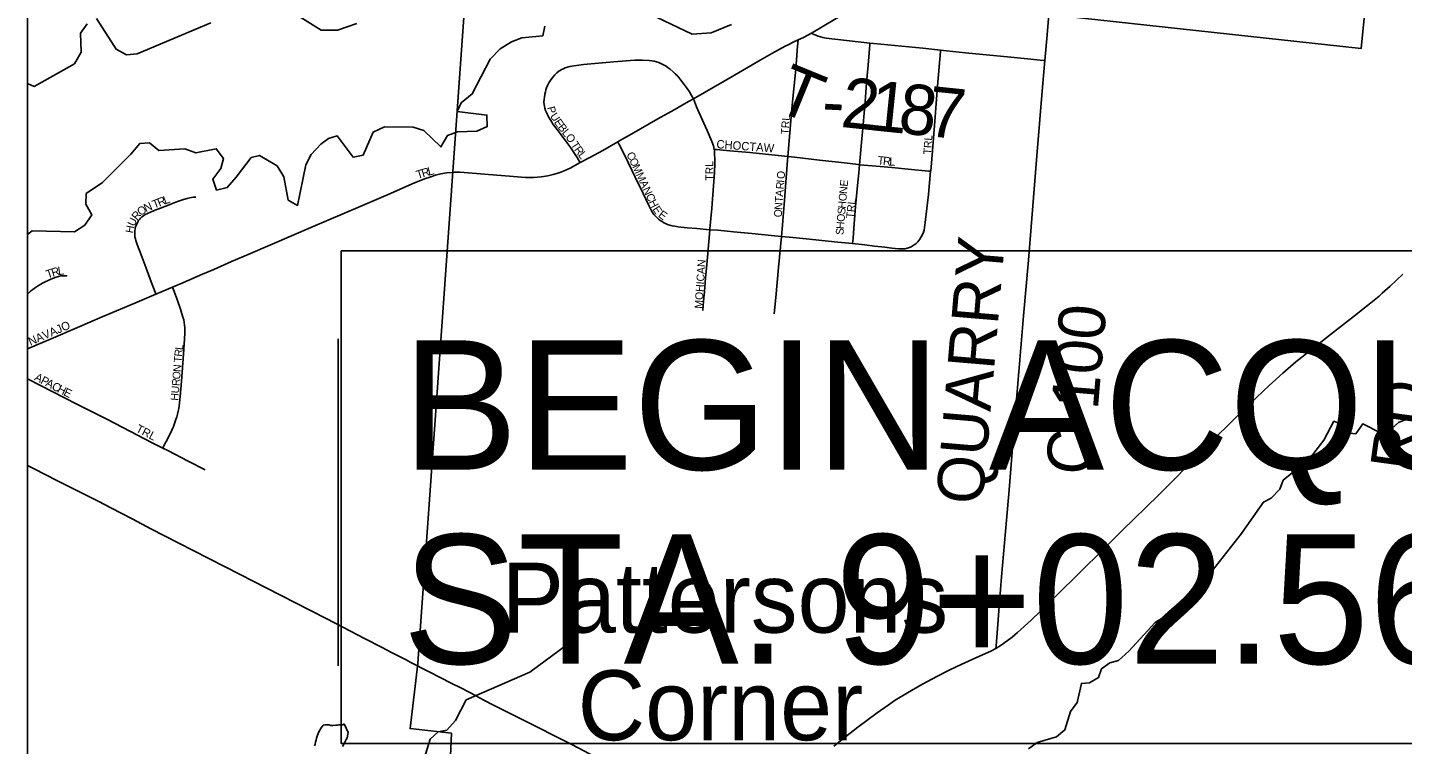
# Model space of a CAD drawing. Extents: x -13.9 to 69.1, y -25.2 to 26.1.
# Drawn here: x 1.757 to 3.245, y 16.445 to 17.221 of the extents above; entities that cross this region are included whole.
import ezdxf

# ---------------------------------------------------------------- set-up
doc = ezdxf.new("R2010")
doc.units = 0
for name, color, linetype in [('Default', 7, 'Continuous'), ('GM_X_Corporation', 7, 'Continuous'), ('GM_X_County_Road', 7, 'Continuous'), ('GM_X_County_Road_Text', 7, 'Continuous'), ('GM_X_Major_Lake', 7, 'Continuous'), ('GM_X_Minor_Lake', 7, 'Continuous'), ('GM_X_Minor_River', 7, 'Continuous'), ('GM_X_Township', 7, 'Continuous'), ('GM_X_Township_Road', 7, 'Continuous'), ('GM_X_Township_Road_Text', 7, 'Continuous'), ('GM_X_Township_Subdivision', 7, 'Continuous'), ('GM_X_Township_Subdivision_Text', 7, 'Continuous'), ('GM_X_Unincorporated_Text', 7, 'Continuous'), ('SH_Data', 7, 'Continuous'), ('SH_Text', 7, 'Continuous')]:
    doc.layers.add(name, color=color, linetype=linetype)

msp = doc.modelspace()

# ---------------------------------------------------------------- linework, layer by layer
at = {"layer": 'Default'}
msp.add_lwpolyline([(2.0933, 16.53), (2.0933, 16.8836)], dxfattribs=at)
at = {"layer": 'GM_X_Corporation'}
msp.add_lwpolyline([(3.2881, 17.4999), (3.2328, 17.5244), (3.2004, 17.1978), (2.8622, 17.2345), (2.8637, 17.2542), (2.8698, 17.3211), (2.9058, 17.3174), (2.9211, 17.4915), (2.9741, 17.4881), (2.979, 17.5484), (2.9644, 17.5499), (2.969, 17.6021), (3.0384, 17.5954), (3.0351, 17.5999), (2.9416, 17.7344), (3.085, 17.8742), (3.0797, 17.8807), (3.2331, 17.8445), (3.2716, 17.8354)], dxfattribs=at)
at = {"layer": 'GM_X_County_Road'}
for points in [[(2.8581, 17.1847), (2.8604, 17.2124), (2.8622, 17.2345)], [(2.8051, 16.5488), (2.8054, 16.5517), (2.8088, 16.5988), (2.8111, 16.626), (2.8164, 16.6876), (2.8193, 16.7202), (2.8223, 16.7569), (2.8267, 16.8097), (2.8299, 16.8481), (2.8351, 16.9085), (2.8402, 16.9689), (2.8494, 17.0815), (2.856, 17.1602), (2.8581, 17.1847)], [(2.8051, 16.5488), (2.8108, 16.5523), (2.8174, 16.5568), (2.8228, 16.561), (2.8284, 16.5658), (2.8431, 16.5794), (2.8633, 16.5988), (2.8768, 16.612), (2.8899, 16.6248), (2.9021, 16.6369), (2.9147, 16.6494), (2.9285, 16.6631), (2.9407, 16.6751), (2.9559, 16.6899), (2.9661, 16.7), (2.9828, 16.7164), (2.9959, 16.7292), (3.032, 16.766), (3.0442, 16.7782), (3.0567, 16.7907), (3.0694, 16.8031), (3.087, 16.8202), (3.1008, 16.8331), (3.1155, 16.8465), (3.1297, 16.8588), (3.1443, 16.8705), (3.1671, 16.8883), (3.1931, 16.9085), (3.2073, 16.9198), (3.2197, 16.93), (3.2231, 16.933), (3.2316, 16.9406), (3.2453, 16.9535)], [(1.7571, 16.7467), (1.7644, 16.7429), (1.7889, 16.7305), (1.8118, 16.7187), (1.8344, 16.7075), (1.8473, 16.7008), (1.8712, 16.6885), (1.8905, 16.6782), (1.9054, 16.6704), (1.9364, 16.6547), (1.9873, 16.6287), (2.0153, 16.6144), (2.0632, 16.5899), (2.0802, 16.5812), (2.0991, 16.5713), (2.1219, 16.5593), (2.1409, 16.5496), (2.1504, 16.5448), (2.1668, 16.5363), (2.1713, 16.5339)], [(2.6298, 16.4431), (2.6422, 16.4531), (2.6556, 16.4635), (2.6766, 16.4789), (2.6885, 16.4875), (2.6959, 16.4927), (2.7094, 16.5008), (2.725, 16.5097), (2.7418, 16.5188), (2.7537, 16.5249), (2.7628, 16.5293), (2.7801, 16.537), (2.794, 16.5431), (2.7996, 16.5458), (2.805, 16.5487), (2.8051, 16.5488)], [(2.1713, 16.5339), (2.1916, 16.5233), (2.2156, 16.5111), (2.2266, 16.5056), (2.2426, 16.4973), (2.2454, 16.4958)], [(2.2454, 16.4958), (2.2599, 16.4882), (2.2774, 16.4793), (2.291, 16.4726), (2.346, 16.4446), (2.3783, 16.4279), (2.4137, 16.4096), (2.4441, 16.3939), (2.471, 16.3799), (2.5073, 16.3611), (2.5227, 16.3528)]]:
    msp.add_lwpolyline(points, dxfattribs=at)
at = {"layer": 'GM_X_Major_Lake'}
for points in [[(2.1136, 17.2249), (2.0925, 17.2178), (2.0749, 17.2175), (2.0327, 17.2439)], [(2.4311, 17.2348), (2.4765, 17.2134), (2.4968, 17.2148), (2.5189, 17.2237)], [(1.8218, 17.2245), (1.8145, 17.2145), (1.8151, 17.1938), (1.8081, 17.1813), (1.7644, 17.1565), (1.7571, 17.1598)], [(1.7571, 16.9967), (1.7622, 17.0004), (1.808, 16.9993), (1.8193, 17.0067), (1.8266, 17.0178), (1.8201, 17.0295), (1.8207, 17.0408), (1.8382, 17.0527), (1.8691, 17.0836), (1.8785, 17.095), (1.889, 17.0958), (1.8992, 17.0876), (1.9273, 17.0891), (1.9393, 17.0848), (1.9613, 17.0894), (1.9692, 17.0787), (1.9663, 17.0678), (1.9576, 17.0564), (1.9618, 17.0447), (1.9733, 17.0473), (1.983, 17.0587), (1.9992, 17.0798), (2.0081, 17.0821), (2.0274, 17.0708), (2.0346, 17.059), (2.0391, 17.0338), (2.0494, 17.0281), (2.0584, 17.0718), (2.0641, 17.083), (2.0744, 17.0943), (2.083, 17.1003), (2.0921, 17.1034), (2.1095, 17.0804), (2.1204, 17.0824), (2.131, 17.1072), (2.1433, 17.1131), (2.1746, 17.1127), (2.186, 17.1091), (2.2045, 17.0913), (2.2115, 17.1035), (2.2224, 17.1076), (2.2433, 17.1085), (2.2546, 17.1133), (2.2542, 17.1257), (2.2219, 17.1297), (2.2264, 17.1391), (2.2384, 17.1486), (2.2578, 17.1863), (2.2685, 17.1973), (2.2808, 17.205), (2.292, 17.2094), (2.3146, 17.2114), (2.3169, 17.2219)], [(1.9554, 17.2254), (1.8758, 17.192), (1.8643, 17.1908), (1.8529, 17.1969), (1.8471, 17.2061), (1.8317, 17.2301)]]:
    msp.add_lwpolyline(points, dxfattribs=at)
at = {"layer": 'GM_X_Minor_Lake'}
for points in [[(2.0997, 16.4673), (2.0983, 16.4662), (2.0963, 16.4659), (2.0939, 16.4659), (2.0923, 16.4656), (2.0906, 16.4656), (2.0875, 16.4653), (2.0855, 16.4653), (2.0835, 16.4661), (2.0818, 16.4661), (2.0794, 16.4661), (2.0771, 16.4658), (2.075, 16.4629), (2.0719, 16.4578), (2.0705, 16.4538), (2.0698, 16.4517), (2.0695, 16.4498), (2.0688, 16.4473), (2.0684, 16.4451), (2.0677, 16.4433)], [(2.0981, 16.4426), (2.0995, 16.4452), (2.1005, 16.4473), (2.1019, 16.4502), (2.1029, 16.452), (2.1036, 16.456), (2.104, 16.4578), (2.0997, 16.4673)]]:
    msp.add_lwpolyline(points, dxfattribs=at)
at = {"layer": 'GM_X_Minor_River'}
for points in [[(3.2591, 16.8007), (3.2408, 16.7933), (3.2298, 16.7833), (3.2207, 16.7824), (3.2023, 16.7918), (3.1947, 16.781), (3.1849, 16.7819), (3.1797, 16.7911), (3.1709, 16.7945), (3.1599, 16.7739), (3.1444, 16.7538), (3.1161, 16.7307), (3.1122, 16.721), (3.103, 16.7113), (3.0945, 16.7071), (3.079, 16.6848), (3.071, 16.6729), (3.0312, 16.6224), (2.9953, 16.5881), (2.9776, 16.5767), (2.9488, 16.5456), (2.9379, 16.5356), (2.9284, 16.5332), (2.9192, 16.5268), (2.916, 16.5174), (2.9065, 16.5114), (2.8977, 16.5108), (2.893, 16.4902), (2.8858, 16.4805), (2.8798, 16.4606), (2.8706, 16.4532), (2.8499, 16.447), (2.8404, 16.4402)], [(2.1864, 16.4298), (2.1928, 16.4504), (2.2014, 16.4586), (2.2108, 16.4603), (2.2204, 16.4707), (2.2319, 16.493), (2.3008, 16.5231), (2.3407, 16.5526)]]:
    msp.add_lwpolyline(points, dxfattribs=at)
at = {"layer": 'GM_X_Township'}
for points in [[(2.2023, 16.145), (2.216, 16.457), (2.1711, 16.462), (2.1794, 16.5325), (2.2304, 17.2467), (2.5714, 18.9023), (2.5995, 20.0118)], [(1.7571, 19.5083), (1.7571, 15.7823)], [(7.8661, 18.459), (4.5288, 18.7816), (2.5714, 18.9023), (2.2304, 17.2467), (2.1794, 16.5325), (2.1711, 16.462), (2.216, 16.457), (2.2023, 16.145)]]:
    msp.add_lwpolyline(points, dxfattribs=at)
at = {"layer": 'GM_X_Township_Road'}
for points in [[(2.6054, 17.2143), (2.6066, 17.2138), (2.6102, 17.2121), (2.6127, 17.211), (2.6154, 17.2103), (2.6179, 17.2097), (2.6213, 17.2091), (2.6687, 17.2037)], [(2.6687, 17.2037), (2.673, 17.2032), (2.7259, 17.1981), (2.7453, 17.196)], [(2.7453, 17.196), (2.7516, 17.1953), (2.7722, 17.1931), (2.8212, 17.1884), (2.8394, 17.1865), (2.8565, 17.1849), (2.8581, 17.1847)]]:
    msp.add_lwpolyline(points, dxfattribs=at)
at = {"layer": 'GM_X_Township_Subdivision'}
for points in [[(2.6054, 17.2143), (2.6304, 17.2292), (2.645, 17.2377), (2.6592, 17.2457), (2.6909, 17.2638), (2.7061, 17.2723), (2.7429, 17.2928), (2.7459, 17.2943)], [(2.4777, 17.1434), (2.511, 17.1624), (2.5309, 17.1741), (2.5498, 17.1851), (2.5626, 17.1923), (2.5769, 17.2002), (2.5811, 17.2023), (2.5856, 17.2046), (2.591, 17.2071)], [(2.58, 17.0811), (2.5821, 17.1065), (2.5843, 17.1328), (2.5884, 17.1753), (2.5904, 17.2002), (2.591, 17.2071)], [(2.591, 17.2071), (2.5911, 17.2071), (2.5968, 17.2098), (2.601, 17.212), (2.6054, 17.2143)], [(2.6574, 17.0721), (2.6598, 17.096), (2.6615, 17.1155), (2.6636, 17.1401), (2.6652, 17.1607), (2.6671, 17.1841), (2.6686, 17.2022), (2.6687, 17.2037)], [(2.7344, 17.065), (2.7345, 17.0653), (2.7356, 17.0781), (2.7388, 17.1145), (2.7412, 17.1478), (2.7424, 17.1615), (2.7453, 17.1945), (2.7453, 17.196)], [(2.3552, 17.0744), (2.3546, 17.0755), (2.352, 17.0797), (2.3491, 17.0843), (2.3451, 17.0903), (2.3419, 17.0948), (2.3391, 17.0985), (2.3366, 17.1019), (2.3334, 17.1059), (2.3313, 17.1086), (2.3261, 17.1155), (2.3233, 17.1198), (2.321, 17.1237), (2.3198, 17.126), (2.3186, 17.1286), (2.3178, 17.1308), (2.3171, 17.1333), (2.3166, 17.1353), (2.3163, 17.1372), (2.316, 17.1398), (2.3162, 17.143), (2.3165, 17.1452), (2.317, 17.1483), (2.3176, 17.151), (2.3181, 17.1532), (2.3189, 17.1553), (2.3199, 17.1578), (2.3213, 17.1607), (2.3228, 17.1629), (2.3244, 17.1654), (2.3258, 17.1673), (2.3276, 17.1693), (2.33, 17.1716), (2.332, 17.1732), (2.3336, 17.1741), (2.3351, 17.175), (2.337, 17.1759), (2.3389, 17.1768), (2.3416, 17.1777), (2.344, 17.1783), (2.3463, 17.1788), (2.3589, 17.1805), (2.3914, 17.1832), (2.4145, 17.185), (2.4227, 17.1852), (2.4298, 17.1848), (2.4327, 17.1845), (2.4354, 17.184), (2.4377, 17.1835), (2.4394, 17.1829), (2.4417, 17.1821), (2.444, 17.181), (2.4461, 17.1799), (2.4483, 17.1786), (2.4505, 17.177), (2.4527, 17.1753), (2.4557, 17.1725), (2.4581, 17.1703), (2.4607, 17.1677), (2.4631, 17.1649), (2.4679, 17.1588), (2.4711, 17.1545), (2.4734, 17.1508), (2.4757, 17.1469), (2.4777, 17.1434)], [(2.396, 17.0969), (2.3987, 17.0985), (2.4085, 17.1041), (2.4417, 17.123), (2.4542, 17.1301), (2.4725, 17.1404), (2.4777, 17.1434)], [(2.5002, 17.0886), (2.4994, 17.0924), (2.4977, 17.0973), (2.4926, 17.1091), (2.4839, 17.1281), (2.4812, 17.1346), (2.4777, 17.1434)], [(2.3552, 17.0744), (2.3657, 17.08), (2.3797, 17.0876), (2.396, 17.0969)], [(2.396, 17.0969), (2.3975, 17.094), (2.4034, 17.0819), (2.4147, 17.0587), (2.4234, 17.0408), (2.429, 17.0285), (2.432, 17.0229), (2.4335, 17.0204), (2.435, 17.0183), (2.4366, 17.0164), (2.4383, 17.0149), (2.44, 17.0131), (2.4419, 17.0117), (2.4438, 17.0105), (2.4457, 17.0093), (2.4477, 17.0084), (2.4498, 17.0075), (2.4521, 17.0067), (2.4546, 17.0061), (2.4577, 17.0054), (2.4611, 17.0049), (2.471, 17.0039), (2.4814, 17.0029), (2.4954, 17.0017)], [(2.4954, 17.0017), (2.4955, 17.0026), (2.4976, 17.0251), (2.5004, 17.0635), (2.5009, 17.0729), (2.5009, 17.0783), (2.5007, 17.0836), (2.5004, 17.0877), (2.5002, 17.0886)], [(2.5002, 17.0886), (2.5028, 17.0884), (2.5173, 17.0872), (2.5387, 17.0851), (2.5696, 17.0822), (2.58, 17.0811)], [(2.2166, 17.0638), (2.2188, 17.064), (2.2254, 17.0641), (2.2515, 17.0619), (2.2832, 17.0593), (2.2959, 17.0584), (2.3052, 17.0584), (2.3129, 17.0589), (2.3201, 17.0599), (2.326, 17.0613), (2.3301, 17.0625), (2.3344, 17.064), (2.3378, 17.0653), (2.3445, 17.0682), (2.3552, 17.0743), (2.3552, 17.0744)], [(2.573, 16.9945), (2.5741, 17.0065), (2.5749, 17.016), (2.5758, 17.029), (2.5797, 17.0769), (2.58, 17.0811)], [(2.58, 17.0811), (2.5871, 17.0803), (2.6141, 17.0771), (2.6379, 17.0743), (2.6535, 17.0725), (2.6574, 17.0721)], [(2.6498, 16.9867), (2.6505, 16.9926), (2.6515, 17.0035), (2.6532, 17.0268), (2.6554, 17.0496), (2.6566, 17.0633), (2.6574, 17.0721)], [(2.6574, 17.0721), (2.6578, 17.0721), (2.6798, 17.0701), (2.6923, 17.0689), (2.71, 17.0673), (2.7321, 17.0652), (2.7344, 17.065)], [(1.914, 16.9397), (1.9258, 16.9447), (1.9463, 16.9536), (1.9586, 16.9588), (1.9779, 16.9672), (1.9986, 16.9761), (2.0427, 16.9951), (2.0663, 17.0053), (2.1171, 17.0269), (2.1499, 17.041), (2.1734, 17.0513), (2.1868, 17.0567), (2.1925, 17.0587), (2.1985, 17.0606), (2.2044, 17.0621), (2.2105, 17.0631), (2.2166, 17.0638)], [(2.6498, 16.9867), (2.6632, 16.9852), (2.6736, 16.984), (2.6849, 16.9827), (2.6925, 16.9818), (2.6996, 16.981), (2.7022, 16.9809), (2.7067, 16.9811), (2.7104, 16.982), (2.7135, 16.9832), (2.7167, 16.9853), (2.7187, 16.9868), (2.7205, 16.9887), (2.7215, 16.99), (2.7227, 16.9916), (2.7242, 16.994), (2.7255, 16.9964), (2.7266, 16.999), (2.7273, 17.0013), (2.7279, 17.0041), (2.7283, 17.0067), (2.7287, 17.0094), (2.732, 17.0398), (2.7344, 17.065)], [(1.896, 16.932), (1.8953, 16.934), (1.8911, 16.9452), (1.8867, 16.9571), (1.88, 16.9746), (1.8757, 16.9856), (1.8742, 16.9901), (1.8738, 16.992), (1.8734, 16.9941), (1.8731, 16.9977), (1.8733, 17.0002), (1.8737, 17.0031), (1.8741, 17.0047), (1.8748, 17.0067), (1.8756, 17.0085), (1.8764, 17.0101), (1.8773, 17.0116), (1.8784, 17.0129), (1.8794, 17.0143), (1.8808, 17.0155), (1.8825, 17.0168), (1.8846, 17.0181), (1.8868, 17.0194), (1.8933, 17.022), (1.9058, 17.027), (1.9121, 17.0294), (1.9193, 17.0323), (1.9228, 17.0334), (1.9259, 17.0344), (1.93, 17.0356), (1.9326, 17.0362), (1.9364, 17.0369), (1.9391, 17.0369)], [(2.4878, 16.9143), (2.4887, 16.9246), (2.4896, 16.9345), (2.4909, 16.9495), (2.4919, 16.9601), (2.4919, 16.9602), (2.4929, 16.9719), (2.4954, 17.0017)], [(2.4954, 17.0017), (2.504, 17.0011), (2.521, 16.9995), (2.5409, 16.9976), (2.5656, 16.9951), (2.573, 16.9945)], [(2.5651, 16.9108), (2.5668, 16.9283), (2.5699, 16.961), (2.573, 16.9945)], [(2.573, 16.9945), (2.5853, 16.9934), (2.6033, 16.9915), (2.6236, 16.9895), (2.6339, 16.9884), (2.6498, 16.9867)], [(1.7571, 16.9319), (1.7603, 16.9351), (1.7643, 16.9383), (1.7656, 16.9392), (1.7679, 16.9408), (1.7733, 16.9438), (1.7825, 16.9481), (1.7882, 16.9504), (1.793, 16.9517), (1.7957, 16.9518), (1.7984, 16.9518), (1.7995, 16.9518), (1.8, 16.9516)], [(1.896, 16.932), (1.9027, 16.9349), (1.914, 16.9397)], [(1.9034, 16.7655), (1.9038, 16.7663), (1.9101, 16.7779), (1.9132, 16.785), (1.915, 16.789), (1.9166, 16.7931), (1.9177, 16.7963), (1.9187, 16.7992), (1.9195, 16.8022), (1.9203, 16.8055), (1.9208, 16.8082), (1.9212, 16.8108), (1.9223, 16.8214), (1.9236, 16.838), (1.926, 16.867), (1.9274, 16.8896), (1.9274, 16.893), (1.9272, 16.8961), (1.927, 16.8985), (1.9266, 16.9014), (1.9261, 16.9043), (1.9253, 16.9072), (1.9227, 16.9156), (1.9189, 16.9262), (1.9157, 16.935), (1.914, 16.9397)], [(1.7571, 16.8728), (1.7826, 16.8838), (1.8113, 16.8958), (1.838, 16.9073), (1.8734, 16.9224), (1.896, 16.932)], [(1.7571, 16.8405), (1.772, 16.833), (1.7964, 16.8203), (1.8118, 16.8123), (1.8328, 16.8018), (1.8428, 16.7967), (1.8602, 16.7877), (1.892, 16.7713), (1.9034, 16.7655)], [(1.9034, 16.7655), (1.909, 16.7627), (1.931, 16.7513), (1.9492, 16.7418)]]:
    msp.add_lwpolyline(points, dxfattribs=at)
at = {"layer": 'SH_Data'}
msp.add_line((1.7571, 21.2145), (1.7571, 14.4145), dxfattribs=at)
at = {"layer": 'SH_Text'}
msp.add_lwpolyline([(2.0965, 16.9789), (3.9826, 16.9789), (3.9826, 16.4459), (2.0965, 16.4459)], close=True, dxfattribs=at)

# ---------------------------------------------------------------- texts
at = {"layer": 'GM_X_County_Road_Text'}
for s, rotation, p in [('QUARRY', 85.181, (2.7907, 16.7033)), ('C-100', 85.1469, (2.9093, 16.735))]:
    msp.add_text(s, height=0.05058, rotation=rotation, dxfattribs=at).set_placement(p)
at = {"layer": 'GM_X_Township_Road_Text'}
for s, height, rotation, p in [('T', 0.0539, 337.8011, (2.5638, 17.1323)), ('2', 0.0543, 353.9353, (2.6361, 17.1131)), ('1', 0.0543, 354.0943, (2.6672, 17.1097)), ('8', 0.0543, 354.1304, (2.6983, 17.1065)), ('7', 0.0543, 354.1379, (2.7293, 17.1033)), ('-', 0.0544, 357.0653, (2.616, 17.1141)), ('RD', 0.05063, 82.1737, (3.2601, 16.7387))]:
    msp.add_text(s, height=height, rotation=rotation, dxfattribs=at).set_placement(p)
at = {"layer": 'GM_X_Township_Subdivision_Text'}
for s, height, rotation, p in [('P', 0.00847, 284.1251, (2.3193, 17.134)), ('U', 0.00863, 302.6386, (2.3222, 17.1248)), ('E', 0.00865, 303.8371, (2.3265, 17.118)), ('B', 0.00869, 307.9911, (2.3304, 17.1123)), ('TRL', 0.00843, 85.9123, (2.5807, 17.1044)), ('L', 0.00872, 310.5994, (2.3349, 17.1064)), ('O', 0.00867, 305.9065, (2.3388, 17.1019)), ('T', 0.00864, 303.4314, (2.3446, 17.0937)), ('CHOCTAW', 0.00906, 355.6038, (2.5024, 17.09)), ('TRL', 0.00843, 85.9123, (2.7349, 17.0829)), ('R', 0.00866, 305.3453, (2.3482, 17.0883)), ('L', 0.00869, 307.3458, (2.3525, 17.0823)), ('C', 0.00856, 294.9462, (2.405, 17.0835)), ('R', 0.00902, 17.0308, (2.185, 17.0582)), ('L', 0.00903, 14.3765, (2.1913, 17.0602)), ('O', 0.00856, 294.959, (2.408, 17.0771)), ('M', 0.00856, 294.9643, (2.4113, 17.07)), ('TRL', 0.00842, 90, (2.4992, 17.0548)), ('T', 0.00906, 354.3791, (2.6766, 17.0725)), ('R', 0.00906, 354.3759, (2.6825, 17.0719)), ('L', 0.00906, 356.9232, (2.6895, 17.0712)), ('T', 0.00901, 17.4744, (2.1793, 17.0565)), ('M', 0.00856, 294.9488, (2.4153, 17.0614)), ('A', 0.00856, 294.959, (2.4193, 17.0529)), ('R', 0.00843, 85.1621, (2.5754, 17.0452)), ('I', 0.00843, 85.1555, (2.576, 17.0523)), ('O', 0.00843, 85.1766, (2.5763, 17.0563)), ('E', 0.00843, 84.7582, (2.6446, 17.0481)), ('L', 0.00899, 21.3821, (1.906, 17.029)), ('N', 0.00856, 294.9628, (2.4226, 17.0457)), ('C', 0.00856, 294.9462, (2.4259, 17.0386)), ('T', 0.00843, 85.4211, (2.5742, 17.0309)), ('A', 0.00843, 85.1776, (2.5747, 17.0372)), ('O', 0.00843, 85.0498, (2.6432, 17.0323)), ('N', 0.00843, 85.034, (2.6439, 17.0402)), ('O', 0.00887, 35.7814, (1.8796, 17.0163)), ('N', 0.00897, 24.3143, (1.8853, 17.0205)), ('T', 0.00899, 21.3748, (1.8942, 17.0244)), ('R', 0.00899, 21.3691, (1.8997, 17.0266)), ('H', 0.00858, 297.0639, (2.4291, 17.0318)), ('E', 0.00863, 302.4876, (2.4331, 17.024)), ('E', 0.00887, 323.9633, (2.4389, 17.0162)), ('O', 0.00843, 87.0114, (2.5733, 17.015)), ('N', 0.00843, 86.5435, (2.5737, 17.023)), ('S', 0.00843, 85.0431, (2.6419, 17.018)), ('H', 0.00843, 85.04, (2.6425, 17.0243)), ('TRL', 0.00843, 83.8746, (2.6513, 17.0136)), ('U', 0.00856, 64.6635, (1.8725, 17.0047)), ('R', 0.00871, 50.6088, (1.8756, 17.0113)), ('H', 0.00843, 85.034, (2.6406, 17.0021)), ('O', 0.00843, 85.034, (2.6412, 17.01)), ('H', 0.00845, 79.137, (1.8712, 16.9975)), ('S', 0.00843, 85.039, (2.64, 16.9957)), ('MOHICAN', 0.00843, 86.0309, (2.4873, 16.9161)), ('T', 0.009, 19.1802, (1.7789, 16.9488)), ('R', 0.00902, 16.4915, (1.7844, 16.9507)), ('L', 0.00905, 8.6634, (1.7906, 16.9525)), ('NAVAJO', 0.00898, 23.4841, (1.7603, 16.8761)), ('L', 0.00844, 82.9911, (1.9251, 16.8712)), ('T', 0.00843, 85.0067, (1.9238, 16.8578)), ('R', 0.00843, 83.9565, (1.9243, 16.8641)), ('A', 0.00894, 332.3341, (1.7638, 16.8394)), ('O', 0.00843, 85.008, (1.9222, 16.8395)), ('N', 0.00843, 85.0137, (1.9229, 16.8475)), ('P', 0.00894, 332.3212, (1.7705, 16.8359)), ('A', 0.00894, 332.3419, (1.7758, 16.8331)), ('C', 0.00894, 332.3225, (1.7825, 16.8296)), ('H', 0.00894, 332.3419, (1.7885, 16.8265)), ('E', 0.00896, 333.9223, (1.7953, 16.8229)), ('U', 0.00843, 85.008, (1.9209, 16.8244)), ('R', 0.00843, 85.0025, (1.9216, 16.8324)), ('H', 0.00843, 85.0137, (1.9202, 16.8165)), ('TRL', 0.00895, 332.7786, (1.8735, 16.7836))]:
    msp.add_text(s, height=height, rotation=rotation, dxfattribs=at).set_placement(p)
at = {"layer": 'GM_X_Unincorporated_Text'}
for s, p in [('Pattersons', (2.2702, 16.5658)), ('Corner', (2.3525, 16.4494))]:
    msp.add_text(s, height=0.07559, rotation=0, dxfattribs=at).set_placement(p)
at = {"layer": 'SH_Text'}
for s, p in [('BEGIN ACQUISTION', (2.1629, 16.7421)), ('STA. 9+02.56', (2.1629, 16.5321))]:
    msp.add_text(s, height=0.14, dxfattribs=at).set_placement(p)

doc.saveas('drawing.dxf')
